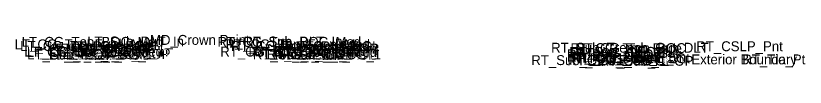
# Model space of a CAD drawing. Extents: x 0 to 6300, y 0 to 9528.
# Drawn here: x 2126 to 2206, y 5518.4 to 5521.9 of the extents above; entities that cross this region are included whole.
import ezdxf

# ---------------------------------------------------------------- set-up
doc = ezdxf.new("R2010")
doc.units = 0
doc.layers.add('Default', color=7, linetype='Continuous')

msp = doc.modelspace()

# ---------------------------------------------------------------- texts
at = {"layer": 'Default'}
for s, p in [('MD_Crown Point', (2139.582, 5520.832)), ('LT_CG_Top_Face_Med', (2125.866, 5520.382)), ('LT_CG_Top_Gut_Med', (2126.418, 5520.216)), ('LT_CG_Top_BOC_Med', (2126.569, 5520.632)), ('LT_PV1_PGL', (2131.503, 5520.201)), ('LT_Sub_DLT_In', (2133.217, 5520.672)), ('RT_CG_Top_BOC_Med', (2146.431, 5520.632)), ('RT_CG_Top_Face_Med', (2147.246, 5520.382)), ('RT_CG_Top_Gut_Med', (2147.8, 5520.216)), ('RT_Sub_DLT_In', (2149.068, 5520.672)), ('RT_PV1_PGL', (2154.385, 5520.201)), ('RT_Sub_Trench_Out_DLT', (2180.257, 5520.042)), ('RT_CG_Top_Face', (2182.225, 5520.001)), ('RT_CG_Top_BOC', (2182.694, 5520.001)), ('RT_CSLP_Pnt', (2194.982, 5520.191)), ('LT_CG_Bot_BOC_Med', (2126.846, 5519.648)), ('LT_CG_Bot_IE_Med', (2127.094, 5519.617)), ('LT_Sub_IEOT_CG_1', (2127.125, 5519.367)), ('LT_PV2_OEEOP', (2129.285, 5519.951)), ('LT_PV3_OEEOP', (2129.285, 5519.701)), ('LT_Sub_OEEOP', (2129.332, 5519.326)), ('LT_PV2_IEEOP', (2130.046, 5519.951)), ('LT_Sub_IEEOP', (2130.093, 5519.326)), ('LT_CG1_Shelf_In', (2130.712, 5519.658)), ('LT_PV2_PGL', (2131.264, 5519.951)), ('LT_Sub_PGL', (2131.311, 5519.326)), ('LT_Sub_IEOP', (2133.045, 5519.412)), ('RT_CG_Bot_BOC_Med', (2146.708, 5519.648)), ('RT_CG1_Shelf_In', (2149.573, 5519.658)), ('RT_CG_Bot_IE_Med', (2149.976, 5519.617)), ('RT_Sub_IEOT_CG_1', (2150.007, 5519.367)), ('RT_Sub_IEOP', (2151.417, 5519.412)), ('RT_PV2_OEEOP', (2152.167, 5519.951)), ('RT_PV3_OEEOP', (2152.167, 5519.701)), ('RT_Sub_OEEOP', (2152.214, 5519.326)), ('RT_PV2_IEEOP', (2152.928, 5519.951)), ('RT_Sub_IEEOP', (2152.975, 5519.326)), ('RT_PV2_PGL', (2154.145, 5519.951)), ('RT_Sub_PGL', (2154.192, 5519.326)), ('RT_PV2_OEOT', (2181.873, 5519.371)), ('RT_PV1_OEOT', (2182.112, 5519.621)), ('RT_CG_Top_Gut', (2182.752, 5519.501)), ('RT_Sub_OEOT_CG_1', (2178.247, 5518.787)), ('RT_PV3_OEOT', (2181.873, 5519.121)), ('RT_Sub_OEOT', (2181.92, 5518.746)), ('RT_CG_Bot_IE', (2182.221, 5519.037)), ('RT_CG1_Shelf_Out', (2182.36, 5518.977)), ('RT_CG_Bot_BOC', (2182.97, 5518.987)), ('RT_Sub_OEOP', (2185.166, 5518.722)), ('Exterior Boundary', (2194.481, 5518.861)), ('RT_Tie_Pt', (2199.643, 5518.861))]:
    msp.add_text(s, height=1, dxfattribs=at).set_placement(p)

doc.saveas('drawing.dxf')
